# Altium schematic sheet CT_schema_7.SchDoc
size 274 x 160 mm
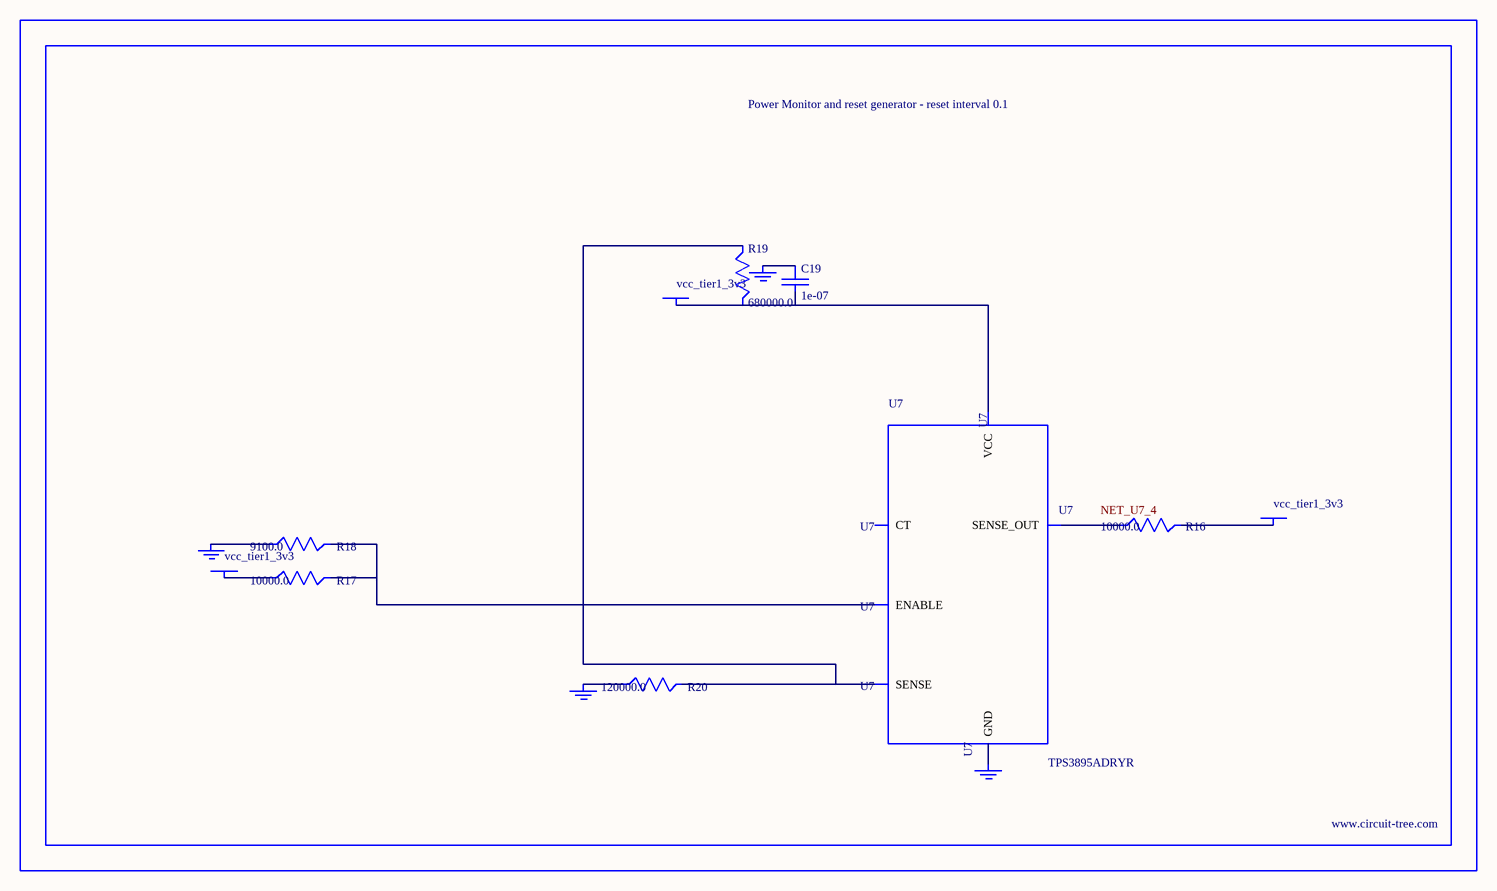
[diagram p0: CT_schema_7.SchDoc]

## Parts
BORDER6  (no value)
C19  1e-07  [C0402]
GND_INSTANCE_6_0  (no value)
GND_INSTANCE_6_1  (no value)
GND_INSTANCE_6_2  (no value)
GND_INSTANCE_6_3  (no value)
POWER_INSTANCE_6_0  vcc_tier1_3v3
POWER_INSTANCE_6_1  vcc_tier1_3v3
POWER_INSTANCE_6_2  vcc_tier1_3v3
R16  10000.0  [R0603]
R17  10000.0  [R0603]
R18  9100.0  [R0603]
R19  680000.0  [R0603]
R20  120000.0  [R0603]
U7  TPS3895ADRYR  [SON-6]

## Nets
NetC19_1: C19.1 GND_INSTANCE_6_2.0(GND)
NetC19_2: C19.2 POWER_INSTANCE_6_2.0(PWR) R19.2 U7.6(VCC)
NetGND_INSTANCE_6_0_0: GND_INSTANCE_6_0.0(GND) R18.1
NetGND_INSTANCE_6_1_0: GND_INSTANCE_6_1.0(GND) R20.1
NetGND_INSTANCE_6_3_0: GND_INSTANCE_6_3.0(GND) U7.2(GND)
NetPOWER_INSTANCE_6_0_0: POWER_INSTANCE_6_0.0(PWR) R17.1
NetPOWER_INSTANCE_6_1_0: POWER_INSTANCE_6_1.0(PWR) R16.2
NetR16_1: R16.1 U7.4(SENSE_OUT)
NetR17_2: R17.2 R18.2 U7.1(ENABLE)
NetR19_1: R19.1 R20.2 U7.3(SENSE)

Not connected (* = marked no-connect by the designer): U7 5(CT)

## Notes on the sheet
- Labels drawn without touching a wire or pin: NET_U7_4

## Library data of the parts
BORDER6 = BORDER_PAGE6
C19 = C0402C104K3RACTU
GND_INSTANCE_6_0-GND_INSTANCE_6_3 = GND
POWER_INSTANCE_6_0-POWER_INSTANCE_6_2 = PWR
R16 R17 = RC0603JR-0710KL
R18 = RC0603JR-079K1L
R19 = RC0603JR-07680KL
R20 = RC0603JR-07120KL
